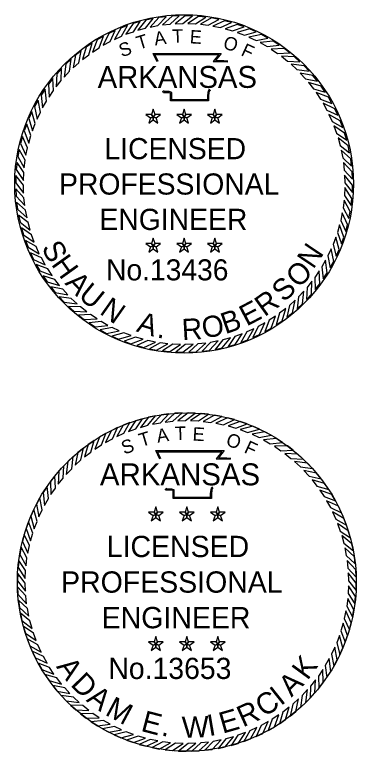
# Model space of a CAD drawing. Extents: x 0 to 19, y -0.6 to 11.5.
# Drawn here: x 17.813 to 19.022, y 4.919 to 7.53 of the extents above; entities that cross this region are included whole.
import ezdxf

# ---------------------------------------------------------------- set-up
doc = ezdxf.new("R2010")
doc.units = 0
for name, color, linetype in [('G-ANNO-STMP', 7, 'Continuous'), ('G-ANNO-SYMB', 7, 'Continuous'), ('G-No Plot-Stamp-1', 7, 'Continuous')]:
    doc.layers.add(name, color=color, linetype=linetype)

msp = doc.modelspace()

# ---------------------------------------------------------------- linework, layer by layer
at = {"layer": 'G-ANNO-STMP'}
for points in [[(18.3581, 6.1156), (18.3325, 6.1123), (18.3011, 6.0787), (18.3285, 6.0839)], [(18.4051, 6.1188), (18.3793, 6.1175), (18.3454, 6.0864), (18.3731, 6.0895)], [(18.4522, 6.1183), (18.4264, 6.119), (18.3902, 6.0907), (18.418, 6.0916)], [(18.4991, 6.1141), (18.4735, 6.1168), (18.4351, 6.0915), (18.463, 6.0902)], [(18.5456, 6.1062), (18.5202, 6.111), (18.48, 6.0887), (18.5077, 6.0852)], [(18.2656, 6.0982), (18.2408, 6.0909), (18.2151, 6.0528), (18.2413, 6.0623)], [(18.3115, 6.1087), (18.2862, 6.1034), (18.2576, 6.0674), (18.2845, 6.0748)], [(18.5913, 6.0947), (18.5664, 6.1015), (18.5245, 6.0824), (18.5518, 6.0768)], [(18.6359, 6.0797), (18.6116, 6.0884), (18.5684, 6.0726), (18.5952, 6.0649)], [(18.1769, 6.0666), (18.1536, 6.0555), (18.1341, 6.0138), (18.1585, 6.0273)], [(18.2206, 6.0841), (18.1965, 6.0749), (18.1738, 6.0349), (18.1992, 6.0464)], [(18.6793, 6.0612), (18.6557, 6.0718), (18.6114, 6.0595), (18.6375, 6.0496)], [(18.1347, 6.0456), (18.1123, 6.0328), (18.0962, 5.9897), (18.1195, 6.005)], [(18.721, 6.0394), (18.6984, 6.0517), (18.6532, 6.043), (18.6784, 6.0311)], [(18.0942, 6.0214), (18.0729, 6.0069), (18.0603, 5.9627), (18.0823, 5.9798)], [(18.7609, 6.0143), (18.7393, 6.0284), (18.6936, 6.0232), (18.7178, 6.0094)], [(18.0558, 5.9942), (18.0357, 5.978), (18.0266, 5.9329), (18.0472, 5.9517)], [(18.7987, 5.9862), (18.7783, 6.002), (18.7323, 6.0004), (18.7554, 5.9847)], [(18.0197, 5.964), (18.0009, 5.9462), (17.9953, 5.9006), (18.0144, 5.9209)], [(18.8342, 5.9552), (18.8151, 5.9726), (18.7692, 5.9746), (18.7909, 5.9571)], [(17.986, 5.931), (17.9687, 5.9119), (17.9667, 5.8659), (17.9841, 5.8877)], [(18.8672, 5.9216), (18.8495, 5.9403), (18.8038, 5.9459), (18.8242, 5.9269)], [(18.8974, 5.8854), (18.8812, 5.9055), (18.8361, 5.9147), (18.8549, 5.8941)], [(17.955, 5.8955), (17.9393, 5.8751), (17.9409, 5.8291), (17.9565, 5.8522)], [(18.9247, 5.847), (18.9101, 5.8683), (18.8659, 5.881), (18.883, 5.859)], [(17.9269, 5.8577), (17.9128, 5.8361), (17.918, 5.7904), (17.9318, 5.8146)], [(18.9489, 5.8066), (18.936, 5.829), (18.893, 5.8451), (18.9083, 5.8218)], [(17.9019, 5.8178), (17.8895, 5.7951), (17.8983, 5.75), (17.9102, 5.7752)], [(18.9698, 5.7644), (18.9588, 5.7877), (18.9171, 5.8071), (18.9305, 5.7827)], [(17.88, 5.776), (17.8695, 5.7525), (17.8818, 5.7082), (17.8916, 5.7342)], [(18.3125, 5.7579), (18.3187, 5.7664), (18.3125, 5.7854), (18.3064, 5.7664)], [(18.4222, 5.7579), (18.4284, 5.7664), (18.4222, 5.7854), (18.4161, 5.7664)], [(18.532, 5.7579), (18.5381, 5.7664), (18.532, 5.7854), (18.5258, 5.7664)], [(18.3125, 5.7579), (18.3064, 5.7664), (18.2864, 5.7664), (18.3026, 5.7547)], [(18.3125, 5.7579), (18.3026, 5.7547), (18.2964, 5.7357), (18.3125, 5.7475)], [(18.3125, 5.7579), (18.3225, 5.7547), (18.3386, 5.7664), (18.3187, 5.7664)], [(18.3125, 5.7579), (18.3125, 5.7475), (18.3286, 5.7357), (18.3225, 5.7547)], [(18.4222, 5.7579), (18.4161, 5.7664), (18.3962, 5.7664), (18.4123, 5.7547)], [(18.4222, 5.7579), (18.4123, 5.7547), (18.4061, 5.7357), (18.4222, 5.7475)], [(18.4222, 5.7579), (18.4322, 5.7547), (18.4483, 5.7664), (18.4284, 5.7664)], [(18.4222, 5.7579), (18.4222, 5.7475), (18.4384, 5.7357), (18.4322, 5.7547)], [(18.532, 5.7579), (18.5258, 5.7664), (18.5059, 5.7664), (18.522, 5.7547)], [(18.532, 5.7579), (18.522, 5.7547), (18.5158, 5.7357), (18.532, 5.7475)], [(18.532, 5.7579), (18.5419, 5.7547), (18.5581, 5.7664), (18.5381, 5.7664)], [(18.532, 5.7579), (18.532, 5.7475), (18.5481, 5.7357), (18.5419, 5.7547)], [(18.9874, 5.7207), (18.9782, 5.7448), (18.9382, 5.7674), (18.9496, 5.742)], [(17.8615, 5.7327), (17.8529, 5.7084), (17.8686, 5.6652), (17.8764, 5.6919)], [(19.0015, 5.6757), (18.9942, 5.7005), (18.9561, 5.7262), (18.9655, 5.6999)], [(17.8465, 5.688), (17.8398, 5.6631), (17.8588, 5.6213), (17.8645, 5.6486)], [(19.012, 5.6298), (19.0067, 5.655), (18.9707, 5.6837), (18.978, 5.6568)], [(17.835, 5.6423), (17.8303, 5.617), (17.8526, 5.5768), (17.856, 5.6044)], [(19.0188, 5.5832), (19.0155, 5.6087), (18.9819, 5.6401), (18.9871, 5.6127)], [(17.8272, 5.5959), (17.8244, 5.5702), (17.8498, 5.5319), (17.8511, 5.5597)], [(19.022, 5.5362), (19.0207, 5.5619), (18.9897, 5.5958), (18.9927, 5.5681)], [(17.823, 5.549), (17.8222, 5.5232), (17.8505, 5.4869), (17.8497, 5.5148)], [(19.0215, 5.489), (19.0223, 5.5148), (18.994, 5.5511), (18.9948, 5.5232)], [(17.8225, 5.5019), (17.8237, 5.4761), (17.8548, 5.4422), (17.8518, 5.4699)], [(19.0173, 5.4421), (19.0201, 5.4678), (18.9947, 5.5061), (18.9934, 5.4783)], [(19.0095, 5.3957), (19.0142, 5.421), (18.9919, 5.4612), (18.9884, 5.4336)], [(17.8256, 5.4548), (17.829, 5.4293), (17.8626, 5.3979), (17.8574, 5.4253)], [(17.8325, 5.4082), (17.8378, 5.383), (17.8738, 5.3544), (17.8665, 5.3812)], [(18.998, 5.35), (19.0047, 5.3749), (18.9856, 5.4167), (18.98, 5.3894)], [(17.843, 5.3623), (17.8503, 5.3376), (17.8884, 5.3118), (17.879, 5.3381)], [(18.9829, 5.3053), (18.9916, 5.3296), (18.9759, 5.3728), (18.9681, 5.3461)], [(18.9645, 5.262), (18.975, 5.2855), (18.9627, 5.3298), (18.9529, 5.3038)], [(17.8571, 5.3173), (17.8663, 5.2932), (17.9063, 5.2706), (17.8949, 5.296)], [(18.3125, 5.2985), (18.3064, 5.307), (18.2864, 5.307), (18.3026, 5.2952)], [(18.3125, 5.2985), (18.3187, 5.307), (18.3125, 5.3259), (18.3064, 5.307)], [(18.3125, 5.2985), (18.3225, 5.2952), (18.3386, 5.307), (18.3187, 5.307)], [(18.4222, 5.2985), (18.4161, 5.307), (18.3962, 5.307), (18.4123, 5.2952)], [(18.4222, 5.2985), (18.4284, 5.307), (18.4222, 5.3259), (18.4161, 5.307)], [(18.4222, 5.2985), (18.4322, 5.2952), (18.4483, 5.307), (18.4284, 5.307)], [(18.532, 5.2985), (18.5258, 5.307), (18.5059, 5.307), (18.522, 5.2952)], [(18.532, 5.2985), (18.5381, 5.307), (18.532, 5.3259), (18.5258, 5.307)], [(18.532, 5.2985), (18.5419, 5.2952), (18.5581, 5.307), (18.5381, 5.307)], [(18.3125, 5.2985), (18.3026, 5.2952), (18.2964, 5.2763), (18.3125, 5.288)], [(18.3125, 5.2985), (18.3125, 5.288), (18.3286, 5.2763), (18.3225, 5.2952)], [(18.4222, 5.2985), (18.4123, 5.2952), (18.4061, 5.2763), (18.4222, 5.288)], [(18.4222, 5.2985), (18.4222, 5.288), (18.4384, 5.2763), (18.4322, 5.2952)], [(18.532, 5.2985), (18.522, 5.2952), (18.5158, 5.2763), (18.532, 5.288)], [(18.532, 5.2985), (18.532, 5.288), (18.5481, 5.2763), (18.5419, 5.2952)], [(18.9426, 5.2202), (18.955, 5.2429), (18.9462, 5.288), (18.9343, 5.2628)], [(17.8747, 5.2736), (17.8857, 5.2503), (17.9274, 5.2309), (17.914, 5.2553)], [(17.8956, 5.2314), (17.9085, 5.209), (17.9515, 5.1929), (17.9362, 5.2162)], [(18.9176, 5.1803), (18.9317, 5.2019), (18.9265, 5.2476), (18.9127, 5.2234)], [(18.8895, 5.1425), (18.9052, 5.1629), (18.9036, 5.2089), (18.888, 5.1858)], [(17.9198, 5.191), (17.9344, 5.1697), (17.9786, 5.157), (17.9615, 5.179)], [(18.8585, 5.107), (18.8758, 5.1261), (18.8778, 5.1721), (18.8604, 5.1503)], [(17.9471, 5.1526), (17.9633, 5.1325), (18.0083, 5.1233), (17.9896, 5.1439)], [(18.8248, 5.0741), (18.8436, 5.0918), (18.8492, 5.1374), (18.8301, 5.1171)], [(17.9773, 5.1164), (17.995, 5.0977), (18.0407, 5.0921), (18.0203, 5.1111)], [(18.7887, 5.0438), (18.8088, 5.06), (18.8179, 5.1051), (18.7973, 5.0863)], [(18.0103, 5.0828), (18.0294, 5.0654), (18.0753, 5.0634), (18.0536, 5.0809)], [(18.7503, 5.0166), (18.7716, 5.0311), (18.7842, 5.0753), (18.7622, 5.0582)], [(18.0458, 5.0518), (18.0662, 5.036), (18.1122, 5.0376), (18.0891, 5.0533)], [(18.7098, 4.9924), (18.7322, 5.0052), (18.7483, 5.0483), (18.725, 5.033)], [(18.0836, 5.0237), (18.1052, 5.0096), (18.1509, 5.0148), (18.1267, 5.0286)], [(18.6676, 4.9714), (18.6909, 4.9825), (18.7104, 5.0242), (18.6859, 5.0107)], [(18.1235, 4.9986), (18.1461, 4.9863), (18.1913, 4.995), (18.166, 5.0069)], [(18.1652, 4.9768), (18.1888, 4.9662), (18.2331, 4.9785), (18.207, 4.9884)], [(18.6239, 4.9539), (18.648, 4.9631), (18.6707, 5.0031), (18.6453, 4.9916)], [(18.2086, 4.9583), (18.2329, 4.9496), (18.2761, 4.9654), (18.2493, 4.9731)], [(18.533, 4.9293), (18.5583, 4.9346), (18.5869, 4.9706), (18.56, 4.9632)], [(18.5789, 4.9398), (18.6037, 4.9471), (18.6294, 4.9852), (18.6032, 4.9757)], [(18.2532, 4.9433), (18.2781, 4.9365), (18.32, 4.9556), (18.2927, 4.9612)], [(18.2989, 4.9318), (18.3243, 4.927), (18.3645, 4.9493), (18.3368, 4.9528)], [(18.3454, 4.9239), (18.371, 4.9212), (18.4094, 4.9465), (18.3815, 4.9478)], [(18.3923, 4.9197), (18.4181, 4.919), (18.4543, 4.9473), (18.4265, 4.9464)], [(18.4394, 4.9192), (18.4652, 4.9205), (18.4991, 4.9516), (18.4714, 4.9485)], [(18.4864, 4.9224), (18.512, 4.9257), (18.5434, 4.9593), (18.516, 4.9541)]]:
    msp.add_lwpolyline(points, close=True, dxfattribs=at)
for points in [[(18.3261, 5.9545), (18.3121, 5.9848), (18.5542, 5.9849), (18.5339, 5.9595), (18.5504, 5.9597), (18.5641, 5.9599), (18.5778, 5.9584)], [(18.3296, 5.9561), (18.3181, 5.981), (18.5462, 5.9811), (18.5259, 5.9556), (18.5504, 5.9559), (18.5639, 5.9561), (18.5774, 5.9546)], [(18.516, 5.8531), (18.5119, 5.8497), (18.5105, 5.8447), (18.5091, 5.8322), (18.5091, 5.8154), (18.374, 5.8154), (18.374, 5.838), (18.374, 5.843), (18.3686, 5.8447), (18.3493, 5.8447), (18.3459, 5.8499)], [(18.5136, 5.856), (18.5085, 5.8519), (18.5067, 5.8454), (18.5053, 5.8324), (18.5053, 5.8193), (18.3779, 5.8193), (18.3779, 5.838), (18.3779, 5.8459), (18.3691, 5.8485), (18.3514, 5.8485), (18.3491, 5.852)]]:
    msp.add_lwpolyline(points, dxfattribs=at)
at = {"layer": 'G-ANNO-SYMB'}
for points in [[(18.3488, 7.5234), (18.3233, 7.5201), (18.2922, 7.4866), (18.3194, 7.4918)], [(18.3955, 7.5265), (18.3699, 7.5252), (18.3362, 7.4944), (18.3637, 7.4974)], [(18.4424, 7.526), (18.4167, 7.5268), (18.3807, 7.4986), (18.4084, 7.4995)], [(18.489, 7.5219), (18.4635, 7.5246), (18.4254, 7.4994), (18.4531, 7.4981)], [(18.2568, 7.5061), (18.2322, 7.4988), (18.2066, 7.4609), (18.2327, 7.4703)], [(18.3024, 7.5165), (18.2773, 7.5112), (18.2489, 7.4755), (18.2756, 7.4828)], [(18.5352, 7.514), (18.51, 7.5188), (18.47, 7.4966), (18.4975, 7.4931)], [(18.5806, 7.5026), (18.5559, 7.5093), (18.5143, 7.4903), (18.5414, 7.4847)], [(18.625, 7.4877), (18.6009, 7.4963), (18.5579, 7.4806), (18.5845, 7.4729)], [(18.1686, 7.4746), (18.1454, 7.4636), (18.1261, 7.4222), (18.1504, 7.4355)], [(18.2121, 7.4921), (18.1881, 7.4829), (18.1656, 7.4431), (18.1908, 7.4546)], [(18.6681, 7.4693), (18.6447, 7.4798), (18.6006, 7.4675), (18.6266, 7.4578)], [(18.1266, 7.4538), (18.1044, 7.441), (18.0884, 7.3982), (18.1115, 7.4134)], [(18.7096, 7.4476), (18.6871, 7.4599), (18.6422, 7.4511), (18.6673, 7.4393)], [(18.0864, 7.4297), (18.0653, 7.4153), (18.0527, 7.3713), (18.0746, 7.3883)], [(18.7493, 7.4227), (18.7278, 7.4367), (18.6824, 7.4315), (18.7065, 7.4178)], [(18.0483, 7.4026), (18.0283, 7.3865), (18.0192, 7.3417), (18.0397, 7.3604)], [(18.7869, 7.3947), (18.7666, 7.4104), (18.7209, 7.4088), (18.7438, 7.3932)], [(18.0123, 7.3726), (17.9937, 7.355), (17.9881, 7.3096), (18.0071, 7.3298)], [(18.8222, 7.3639), (18.8032, 7.3811), (18.7575, 7.3831), (18.7791, 7.3658)], [(17.9788, 7.3398), (17.9616, 7.3208), (17.9596, 7.2751), (17.977, 7.2967)], [(18.855, 7.3304), (18.8374, 7.3491), (18.792, 7.3547), (18.8122, 7.3357)], [(18.885, 7.2945), (18.8689, 7.3145), (18.8241, 7.3236), (18.8428, 7.3031)], [(17.948, 7.3045), (17.9324, 7.2842), (17.934, 7.2385), (17.9495, 7.2614)], [(18.9121, 7.2563), (18.8977, 7.2775), (18.8537, 7.2901), (18.8707, 7.2682)], [(17.9201, 7.2669), (17.9061, 7.2454), (17.9113, 7.2), (17.925, 7.2241)], [(18.9362, 7.2161), (18.9234, 7.2384), (18.8806, 7.2544), (18.8958, 7.2312)], [(17.8952, 7.2272), (17.8829, 7.2047), (17.8916, 7.1598), (17.9034, 7.1849)], [(18.957, 7.1742), (18.946, 7.1973), (18.9046, 7.2167), (18.9179, 7.1924)], [(17.8735, 7.1857), (17.863, 7.1623), (17.8752, 7.1183), (17.885, 7.1442)], [(18.3035, 7.1677), (18.3096, 7.1762), (18.3035, 7.195), (18.2974, 7.1762)], [(18.4126, 7.1677), (18.4187, 7.1762), (18.4126, 7.195), (18.4065, 7.1762)], [(18.5217, 7.1677), (18.5278, 7.1762), (18.5217, 7.195), (18.5155, 7.1762)], [(18.3035, 7.1677), (18.2974, 7.1762), (18.2775, 7.1762), (18.2936, 7.1645)], [(18.3035, 7.1677), (18.2936, 7.1645), (18.2875, 7.1457), (18.3035, 7.1573)], [(18.3035, 7.1677), (18.3134, 7.1645), (18.3294, 7.1762), (18.3096, 7.1762)], [(18.3035, 7.1677), (18.3035, 7.1573), (18.3195, 7.1457), (18.3134, 7.1645)], [(18.4126, 7.1677), (18.4065, 7.1762), (18.3866, 7.1762), (18.4027, 7.1645)], [(18.4126, 7.1677), (18.4027, 7.1645), (18.3965, 7.1457), (18.4126, 7.1573)], [(18.4126, 7.1677), (18.4225, 7.1645), (18.4385, 7.1762), (18.4187, 7.1762)], [(18.4126, 7.1677), (18.4126, 7.1573), (18.4286, 7.1457), (18.4225, 7.1645)], [(18.5217, 7.1677), (18.5155, 7.1762), (18.4957, 7.1762), (18.5118, 7.1645)], [(18.5217, 7.1677), (18.5118, 7.1645), (18.5056, 7.1457), (18.5217, 7.1573)], [(18.5217, 7.1677), (18.5316, 7.1645), (18.5476, 7.1762), (18.5278, 7.1762)], [(18.5217, 7.1677), (18.5217, 7.1573), (18.5377, 7.1457), (18.5316, 7.1645)], [(18.9745, 7.1307), (18.9653, 7.1547), (18.9255, 7.1772), (18.9369, 7.1519)], [(17.8551, 7.1426), (17.8465, 7.1185), (17.8621, 7.0755), (17.8698, 7.1021)], [(18.9885, 7.086), (18.9812, 7.1106), (18.9433, 7.1362), (18.9527, 7.1101)], [(17.8401, 7.0982), (17.8334, 7.0735), (17.8524, 7.0319), (17.858, 7.059)], [(18.9989, 7.0403), (18.9936, 7.0654), (18.9579, 7.0939), (18.9652, 7.0672)], [(17.8287, 7.0528), (17.824, 7.0276), (17.8462, 6.9876), (17.8496, 7.0151)], [(19.0058, 6.994), (19.0025, 7.0194), (18.969, 7.0506), (18.9742, 7.0234)], [(17.8209, 7.0066), (17.8182, 6.9811), (17.8434, 6.943), (17.8447, 6.9707)], [(19.0089, 6.9472), (19.0076, 6.9729), (18.9768, 7.0066), (18.9798, 6.979)], [(17.8167, 6.96), (17.816, 6.9343), (17.8441, 6.8983), (17.8433, 6.926)], [(19.0084, 6.9004), (19.0092, 6.926), (18.981, 6.9621), (18.9819, 6.9344)], [(17.8162, 6.9131), (17.8175, 6.8875), (17.8484, 6.8538), (17.8454, 6.8813)], [(19.0043, 6.8537), (19.007, 6.8792), (18.9818, 6.9174), (18.9805, 6.8897)], [(18.9964, 6.8075), (19.0012, 6.8328), (18.979, 6.8728), (18.9755, 6.8453)], [(17.8194, 6.8664), (17.8227, 6.841), (17.8561, 6.8098), (17.8509, 6.837)], [(17.8262, 6.8201), (17.8315, 6.7949), (17.8673, 6.7665), (17.86, 6.7932)], [(18.985, 6.7621), (18.9917, 6.7869), (18.9727, 6.8285), (18.9671, 6.8014)], [(17.8367, 6.7744), (17.8439, 6.7498), (17.8818, 6.7242), (17.8724, 6.7503)], [(18.9701, 6.7177), (18.9787, 6.7419), (18.963, 6.7849), (18.9553, 6.7582)], [(18.3035, 6.7109), (18.3096, 6.7194), (18.3035, 6.7382), (18.2974, 6.7194)], [(18.4126, 6.7109), (18.4187, 6.7194), (18.4126, 6.7382), (18.4065, 6.7194)], [(18.5217, 6.7109), (18.5278, 6.7194), (18.5217, 6.7382), (18.5155, 6.7194)], [(18.9517, 6.6746), (18.9622, 6.6981), (18.9499, 6.7421), (18.9401, 6.7162)], [(17.8507, 6.7297), (17.8598, 6.7057), (17.8996, 6.6832), (17.8882, 6.7085)], [(18.3035, 6.7109), (18.2974, 6.7194), (18.2775, 6.7194), (18.2936, 6.7077)], [(18.3035, 6.7109), (18.3134, 6.7077), (18.3294, 6.7194), (18.3096, 6.7194)], [(18.4126, 6.7109), (18.4065, 6.7194), (18.3866, 6.7194), (18.4027, 6.7077)], [(18.4126, 6.7109), (18.4225, 6.7077), (18.4385, 6.7194), (18.4187, 6.7194)], [(18.5217, 6.7109), (18.5155, 6.7194), (18.4957, 6.7194), (18.5118, 6.7077)], [(18.5217, 6.7109), (18.5316, 6.7077), (18.5476, 6.7194), (18.5278, 6.7194)], [(17.8681, 6.6862), (17.8791, 6.663), (17.9206, 6.6437), (17.9072, 6.668)], [(18.3035, 6.7109), (18.2936, 6.7077), (18.2875, 6.6889), (18.3035, 6.7005)], [(18.3035, 6.7109), (18.3035, 6.7005), (18.3195, 6.6889), (18.3134, 6.7077)], [(18.4126, 6.7109), (18.4027, 6.7077), (18.3965, 6.6889), (18.4126, 6.7005)], [(18.4126, 6.7109), (18.4126, 6.7005), (18.4286, 6.6889), (18.4225, 6.7077)], [(18.5217, 6.7109), (18.5118, 6.7077), (18.5056, 6.6889), (18.5217, 6.7005)], [(18.5217, 6.7109), (18.5217, 6.7005), (18.5377, 6.6889), (18.5316, 6.7077)], [(18.93, 6.6331), (18.9423, 6.6556), (18.9335, 6.7005), (18.9217, 6.6755)], [(18.9051, 6.5935), (18.9191, 6.6149), (18.9139, 6.6604), (18.9002, 6.6363)], [(17.889, 6.6443), (17.9017, 6.622), (17.9446, 6.606), (17.9294, 6.6292)], [(18.8771, 6.5559), (18.8928, 6.5762), (18.8912, 6.6219), (18.8756, 6.5989)], [(17.913, 6.6041), (17.9275, 6.5829), (17.9715, 6.5703), (17.9545, 6.5922)], [(18.8463, 6.5206), (18.8635, 6.5396), (18.8655, 6.5853), (18.8482, 6.5636)], [(17.9401, 6.5659), (17.9562, 6.5459), (18.0011, 6.5368), (17.9824, 6.5573)], [(17.9702, 6.5299), (17.9878, 6.5113), (18.0332, 6.5057), (18.013, 6.5247)], [(18.8128, 6.4878), (18.8315, 6.5054), (18.8371, 6.5508), (18.8181, 6.5306)], [(18.7769, 6.4577), (18.7969, 6.4738), (18.806, 6.5187), (18.7855, 6.5)], [(18.003, 6.4964), (18.022, 6.4792), (18.0677, 6.4772), (18.046, 6.4946)], [(18.7387, 6.4306), (18.7599, 6.4451), (18.7725, 6.4891), (18.7506, 6.4721)], [(18.0382, 6.4656), (18.0586, 6.45), (18.1043, 6.4516), (18.0813, 6.4671)], [(18.6985, 6.4066), (18.7208, 6.4193), (18.7368, 6.4622), (18.7136, 6.447)], [(18.0758, 6.4377), (18.0973, 6.4237), (18.1428, 6.4289), (18.1187, 6.4426)], [(18.6565, 6.3858), (18.6797, 6.3967), (18.699, 6.4382), (18.6748, 6.4248)], [(18.1155, 6.4128), (18.138, 6.4005), (18.1829, 6.4092), (18.1578, 6.421)], [(18.157, 6.3911), (18.1804, 6.3806), (18.2245, 6.3928), (18.1986, 6.4026)], [(18.5684, 6.3543), (18.593, 6.3615), (18.6186, 6.3994), (18.5925, 6.39)], [(18.6131, 6.3683), (18.637, 6.3774), (18.6596, 6.4172), (18.6343, 6.4058)], [(18.2001, 6.3727), (18.2243, 6.3641), (18.2673, 6.3797), (18.2406, 6.3874)], [(18.2445, 6.3578), (18.2693, 6.3511), (18.3109, 6.37), (18.2837, 6.3756)], [(18.4764, 6.337), (18.5018, 6.3403), (18.533, 6.3737), (18.5058, 6.3685)], [(18.5227, 6.3438), (18.5478, 6.3491), (18.5763, 6.3849), (18.5495, 6.3776)], [(18.2899, 6.3463), (18.3152, 6.3416), (18.3552, 6.3638), (18.3277, 6.3672)], [(18.3361, 6.3385), (18.3616, 6.3358), (18.3998, 6.361), (18.3721, 6.3623)], [(18.3828, 6.3343), (18.4084, 6.3336), (18.4445, 6.3618), (18.4168, 6.3609)], [(18.4296, 6.3338), (18.4553, 6.3351), (18.489, 6.366), (18.4614, 6.363)]]:
    msp.add_lwpolyline(points, close=True, dxfattribs=at)
for points in [[(18.317, 7.3632), (18.3031, 7.3933), (18.5437, 7.3934), (18.5236, 7.3682), (18.54, 7.3684), (18.5536, 7.3686), (18.5673, 7.3671)], [(18.3205, 7.3648), (18.309, 7.3895), (18.5358, 7.3896), (18.5156, 7.3643), (18.54, 7.3646), (18.5534, 7.3648), (18.5669, 7.3633)], [(18.5058, 7.2623), (18.5017, 7.259), (18.5003, 7.254), (18.499, 7.2415), (18.499, 7.2249), (18.3647, 7.2249), (18.3647, 7.2474), (18.3647, 7.2523), (18.3592, 7.254), (18.3401, 7.254), (18.3367, 7.2592)], [(18.5034, 7.2653), (18.4984, 7.2612), (18.4966, 7.2547), (18.4952, 7.2417), (18.4952, 7.2287), (18.3685, 7.2287), (18.3685, 7.2474), (18.3685, 7.2552), (18.3598, 7.2578), (18.3422, 7.2578), (18.3399, 7.2613)]]:
    msp.add_lwpolyline(points, dxfattribs=at)
at = {"layer": 'G-No Plot-Stamp-1'}
for centre in [(18.4126, 6.9304), (18.4222, 5.519)]:
    msp.add_circle(centre, 0.6, dxfattribs=at)

# ---------------------------------------------------------------- texts
at = {"layer": 'G-ANNO-STMP'}
for s, height, rotation, p in [('A', 0.0477, 8.6788, (18.3187, 6.0128)), ('T', 0.0477, 1.4789, (18.3804, 6.0223)), ('E', 0.0477, 356.672, (18.4415, 6.0208)), ('T', 0.0477, 16.9015, (18.2608, 5.9976)), ('O', 0.0477, 341.2218, (18.5574, 6.0044)), ('S', 0.0477, 19.7726, (18.2001, 5.9704)), ('F', 0.0477, 335.3628, (18.6218, 5.9793)), ('K', 0.0754, 53.8471, (18.8495, 5.1679)), ('A', 0.0754, 305.982, (17.958, 5.2187)), ('D', 0.0754, 314.3022, (18.0075, 5.1535)), ('A', 0.0754, 45.185, (18.7929, 5.1088)), ('I', 0.0754, 38.4057, (18.7549, 5.0781)), ('A', 0.0754, 322.6223, (18.0634, 5.0983)), ('C', 0.0754, 32.1396, (18.695, 5.0383)), ('M', 0.0754, 331.7969, (18.1293, 5.0496)), ('R', 0.0754, 24.1616, (18.6211, 5.0031)), ('E', 0.0754, 16.0125, (18.5491, 4.981)), ('E', 0.0754, 345.2782, (18.2564, 4.9917)), ('W', 0.0754, 2.1127, (18.4063, 4.9659)), ('I', 0.0754, 9.5753, (18.5011, 4.9724)), ('.', 0.0754, 350.8583, (18.3296, 4.9747))]:
    msp.add_text(s, height=height, rotation=rotation, dxfattribs=at).set_placement(p)
for s, height, p in [('ARKANSAS', 0.07792, (18.1143, 5.8618)), ('LICENSED', 0.07543, (18.1385, 5.6074)), ('PROFESSIONAL', 0.075433, (17.9768, 5.4813)), ('ENGINEER', 0.07543, (18.1205, 5.3551)), ('No.13653', 0.07514, (18.1443, 5.1753))]:
    msp.add_text(s, height=height, dxfattribs=at).set_placement(p)
at = {"layer": 'G-ANNO-SYMB'}
for s, height, rotation, p in [('A', 0.0475, 8.6788, (18.3097, 7.4211)), ('T', 0.0475, 1.4789, (18.371, 7.4306)), ('E', 0.0475, 356.672, (18.4317, 7.4291)), ('T', 0.0475, 16.9015, (18.252, 7.4061)), ('O', 0.0475, 341.2218, (18.547, 7.4128)), ('S', 0.0475, 19.7726, (18.1917, 7.379)), ('F', 0.0475, 335.3628, (18.6109, 7.3878)), ('ARKANSAS', 0.07747, 360, (18.1064, 7.271)), ('LICENSED', 0.075, 360, (18.1304, 7.0181)), ('PROFESSIONAL', 0.075, 360, (17.9697, 6.8927)), ('ENGINEER', 0.075, 360, (18.1126, 6.7673)), ('S', 0.075, 298.1636, (17.9058, 6.7042)), ('N', 0.075, 56.1007, (18.87, 6.6258)), ('H', 0.075, 305.619, (17.94, 6.6454)), ('No.13436', 0.0747, 360, (18.1363, 6.5885)), ('O', 0.075, 44.7757, (18.8179, 6.5583)), ('A', 0.075, 313.4472, (17.9876, 6.577)), ('U', 0.075, 320.9026, (18.0343, 6.5281)), ('S', 0.075, 43.4878, (18.7664, 6.5086)), ('N', 0.075, 324.9326, (18.1099, 6.4722)), ('R', 0.075, 35.6597, (18.6974, 6.4576)), ('E', 0.075, 27.8315, (18.634, 6.4244)), ('B', 0.075, 18.885, (18.5583, 6.3973)), ('A', 0.075, 343.0991, (18.2407, 6.4079)), ('R', 0.075, 3.2287, (18.4063, 6.3765)), ('O', 0.075, 11.4296, (18.4831, 6.3814)), ('.', 0.075, 351.3, (18.3144, 6.386))]:
    msp.add_text(s, height=height, rotation=rotation, dxfattribs=at).set_placement(p)

doc.saveas('drawing.dxf')
